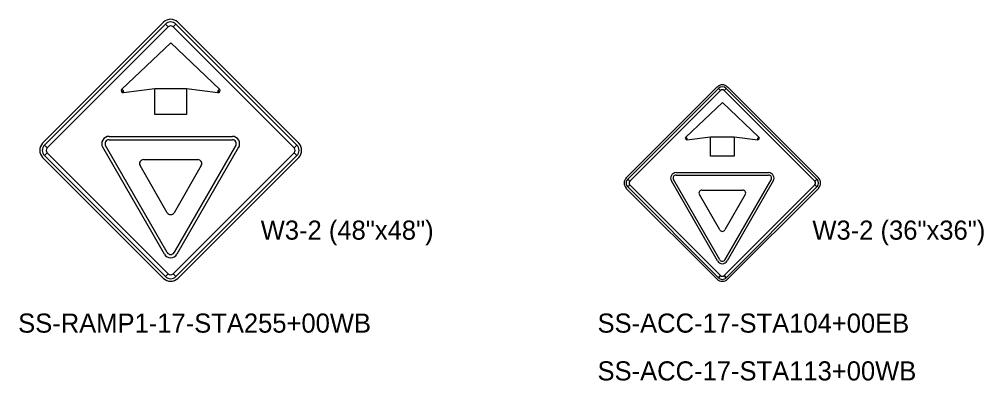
# Model space of a CAD drawing. Extents: x 620856.8 to 620948.6, y 415598.8 to 415658.2.
# Drawn here: x 620878.89 to 620899.08, y 415603 to 415610.56 of the extents above; entities that cross this region are included whole.
import ezdxf

# ---------------------------------------------------------------- set-up
doc = ezdxf.new("R2010")
doc.units = 0
doc.layers.add('SIGNS', color=7, linetype='Continuous')

msp = doc.modelspace()

# ---------------------------------------------------------------- linework, layer by layer
at = {"layer": 'SIGNS'}
for p, q in [((620879.382, 415607.965), (620881.916, 415610.499)), ((620881.955, 415610.459), (620882.014, 415610.4)), ((620882.112, 415610.4), (620882.171, 415610.459)), ((620882.21, 415610.499), (620884.744, 415607.965)), ((620881.07, 415609.067), (620881.041, 415609.097)), ((620881.075, 415609.026), (620881.07, 415609.067)), ((620883.056, 415609.067), (620883.051, 415609.026)), ((620883.085, 415609.097), (620883.056, 415609.067)), ((620891.601, 415607.242), (620893.501, 415609.143)), ((620893.531, 415609.113), (620893.575, 415609.069)), ((620893.649, 415609.069), (620893.693, 415609.113)), ((620893.722, 415609.143), (620895.623, 415607.242)), ((620880.772, 415608.109), (620883.354, 415608.109)), ((620880.772, 415608.04), (620883.354, 415608.04)), ((620892.867, 415608.069), (620892.845, 415608.092)), ((620892.871, 415608.038), (620892.867, 415608.069)), ((620894.357, 415608.069), (620894.353, 415608.038)), ((620894.378, 415608.092), (620894.357, 415608.069)), ((620879.48, 415607.867), (620879.421, 415607.926)), ((620879.421, 415607.709), (620879.48, 415607.768)), ((620881.931, 415605.644), (620880.64, 415607.88)), ((620881.991, 415605.679), (620880.7, 415607.915)), ((620882.135, 415605.679), (620883.426, 415607.915)), ((620883.426, 415607.915), (620882.135, 415605.679)), ((620883.426, 415607.915), (620882.135, 415605.679)), ((620883.486, 415607.88), (620882.195, 415605.644)), ((620884.705, 415607.926), (620884.646, 415607.867)), ((620884.646, 415607.768), (620884.705, 415607.709)), ((620881.916, 415605.136), (620879.382, 415607.67)), ((620881.494, 415607.623), (620882.632, 415607.623)), ((620884.744, 415607.67), (620882.21, 415605.136)), ((620881.991, 415606.512), (620881.421, 415607.498)), ((620882.704, 415607.498), (620882.135, 415606.512)), ((620892.644, 415607.351), (620894.58, 415607.351)), ((620891.675, 415607.169), (620891.631, 415607.213)), ((620893.513, 415605.502), (620892.545, 415607.179)), ((620893.558, 415605.528), (620892.59, 415607.205)), ((620892.644, 415607.299), (620894.58, 415607.299)), ((620893.666, 415605.528), (620894.634, 415607.205)), ((620894.634, 415607.205), (620893.666, 415605.528)), ((620894.634, 415607.205), (620893.666, 415605.528)), ((620894.679, 415607.179), (620893.711, 415605.502)), ((620895.593, 415607.213), (620895.549, 415607.169)), ((620893.501, 415605.121), (620891.601, 415607.021)), ((620891.631, 415607.051), (620891.675, 415607.095)), ((620893.185, 415606.986), (620894.039, 415606.986)), ((620895.623, 415607.021), (620893.722, 415605.121)), ((620895.549, 415607.095), (620895.593, 415607.051)), ((620893.558, 415606.153), (620893.131, 415606.892)), ((620894.093, 415606.892), (620893.666, 415606.153)), ((620882.014, 415605.235), (620881.955, 415605.176)), ((620882.171, 415605.176), (620882.112, 415605.235)), ((620893.575, 415605.195), (620893.531, 415605.151)), ((620893.693, 415605.151), (620893.649, 415605.195))]:
    msp.add_line(p, q, dxfattribs=at)
for points in [[(620881.955, 415610.459), (620879.421, 415607.926), (620879.48, 415607.867), (620882.014, 415610.4), (620881.955, 415610.459), (620881.955, 415610.459)], [(620884.705, 415607.926), (620882.171, 415610.459), (620882.112, 415610.4), (620884.646, 415607.867), (620884.705, 415607.926), (620884.705, 415607.926)], [(620882.063, 415610.067), (620881.041, 415609.097), (620881.07, 415609.067), (620881.075, 415609.026), (620881.73, 415609.109), (620882.396, 415609.109), (620883.051, 415609.026), (620883.056, 415609.067), (620883.085, 415609.097), (620882.063, 415610.067), (620882.063, 415610.067)], [(620882.396, 415608.567), (620881.73, 415608.567), (620881.73, 415609.109), (620882.396, 415609.109), (620882.396, 415608.567), (620882.396, 415608.567)], [(620893.531, 415609.113), (620891.631, 415607.213), (620891.675, 415607.169), (620893.575, 415609.069), (620893.531, 415609.113), (620893.531, 415609.113)], [(620895.593, 415607.213), (620893.693, 415609.113), (620893.649, 415609.069), (620895.549, 415607.169), (620895.593, 415607.213), (620895.593, 415607.213)], [(620893.612, 415608.819), (620892.845, 415608.092), (620892.867, 415608.069), (620892.871, 415608.038), (620893.362, 415608.101), (620893.862, 415608.101), (620894.353, 415608.038), (620894.357, 415608.069), (620894.378, 415608.092), (620893.612, 415608.819), (620893.612, 415608.819)], [(620893.862, 415607.694), (620893.362, 415607.694), (620893.362, 415608.101), (620893.862, 415608.101), (620893.862, 415607.694), (620893.862, 415607.694)], [(620879.421, 415607.709), (620881.955, 415605.176), (620882.014, 415605.235), (620879.48, 415607.768), (620879.421, 415607.709), (620879.421, 415607.709)], [(620882.171, 415605.176), (620884.705, 415607.709), (620884.646, 415607.768), (620882.112, 415605.235), (620882.171, 415605.176), (620882.171, 415605.176)], [(620891.631, 415607.051), (620893.531, 415605.151), (620893.575, 415605.195), (620891.675, 415607.095), (620891.631, 415607.051), (620891.631, 415607.051)], [(620893.693, 415605.151), (620895.593, 415607.051), (620895.549, 415607.095), (620893.649, 415605.195), (620893.693, 415605.151), (620893.693, 415605.151)]]:
    msp.add_lwpolyline(points, close=True, dxfattribs=at)
for centre, radius, start, end in [((620882.063, 415610.351), 0.208, 45, 134.9997), ((620882.063, 415610.351), 0.153, 45, 134.9997), ((620882.063, 415610.351), 0.0694, 45, 134.9997), ((620893.612, 415609.032), 0.156, 45, 134.9997), ((620881.07, 415609.067), 0.0417, 133.9805, 277.2279), ((620883.056, 415609.067), 0.0417, 262.7722, 46.0197), ((620893.612, 415609.032), 0.115, 45, 134.9997), ((620893.612, 415609.032), 0.0521, 45, 134.9997), ((620879.529, 415607.817), 0.208, 134.9997, 225), ((620880.772, 415607.956), 0.153, 90.0002, 209.9999), ((620880.772, 415607.956), 0.0833, 90.0002, 209.9999), ((620883.354, 415607.956), 0.153, 330.0002, 89.9999), ((620883.354, 415607.956), 0.0833, 329.9996, 89.9999), ((620884.597, 415607.817), 0.208, 315.0002, 44.9998), ((620892.867, 415608.069), 0.0313, 133.9805, 277.2279), ((620894.357, 415608.069), 0.0313, 262.7722, 46.0197), ((620879.529, 415607.817), 0.153, 134.9997, 225), ((620879.529, 415607.817), 0.0694, 134.9997, 225), ((620884.597, 415607.817), 0.0694, 315.0002, 44.9998), ((620884.597, 415607.817), 0.153, 315.0002, 44.9998), ((620881.494, 415607.54), 0.0833, 90.0002, 209.9999), ((620882.632, 415607.54), 0.0833, 330.0002, 89.9999), ((620892.644, 415607.236), 0.115, 90.0002, 209.9999), ((620894.58, 415607.236), 0.115, 330.0002, 89.9999), ((620891.712, 415607.132), 0.156, 134.9997, 225), ((620891.712, 415607.132), 0.115, 134.9997, 225), ((620891.712, 415607.132), 0.0521, 134.9997, 225), ((620892.644, 415607.236), 0.0625, 90.0002, 209.9999), ((620894.58, 415607.236), 0.0625, 329.9996, 89.9999), ((620895.512, 415607.132), 0.0521, 315.0002, 44.9998), ((620895.512, 415607.132), 0.115, 315.0002, 44.9998), ((620895.512, 415607.132), 0.156, 315.0002, 44.9998), ((620893.185, 415606.924), 0.0625, 90.0002, 209.9999), ((620894.039, 415606.924), 0.0625, 330.0002, 89.9999), ((620882.063, 415606.554), 0.0833, 209.9999, 330.0002), ((620893.612, 415606.184), 0.0625, 209.9999, 330.0002), ((620882.063, 415605.72), 0.153, 210.0005, 330.0002), ((620882.063, 415605.72), 0.0833, 209.9999, 330.0002), ((620893.612, 415605.559), 0.115, 210.0005, 330.0002), ((620893.612, 415605.559), 0.0625, 209.9999, 330.0002), ((620882.063, 415605.284), 0.208, 225, 315.0002), ((620882.063, 415605.284), 0.153, 225, 315.0002), ((620882.063, 415605.284), 0.0694, 225, 315.0002), ((620893.612, 415605.232), 0.115, 225, 315.0002), ((620893.612, 415605.232), 0.0521, 225, 315.0002), ((620893.612, 415605.232), 0.156, 225, 315.0002)]:
    msp.add_arc(centre, radius, start, end, dxfattribs=at)

# ---------------------------------------------------------------- texts
for s, p in [('W3-2 (48"x48")', (620883.948, 415605.947)), ('W3-2 (36"x36")', (620895.497, 415605.947)), ('SS-RAMP1-17-STA255+00WB', (620878.87, 415604.001)), ('SS-ACC-17-STA104+00EB', (620890.999, 415604.001)), ('SS-ACC-17-STA113+00WB', (620890.999, 415603.001))]:
    msp.add_text(s, height=0.4, rotation=0, dxfattribs=at).set_placement(p)

doc.saveas('drawing.dxf')
